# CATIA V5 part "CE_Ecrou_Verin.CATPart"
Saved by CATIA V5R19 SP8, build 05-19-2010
Part number: CE6_Ecrou_Verin
Nomenclature: 70_m
Bounding box of the stored display mesh (mm): x -18 to 18, y -17.75 to 17.75, z 15 to 135
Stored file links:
  C:\Users\rphgr\Desktop\0_Tapis_TC520B_vitesse\CE_Ecrou_Verin.CATPart
  D:\Documents\1_Travail\1 - ac-limoges.fr\ac-limoges.fr\Emmanuel Maynard - STI2D_Turgot\3 - Supports\Tapis de course TC520B\Tapis de course TC520B_Ca\Vis.CATPart
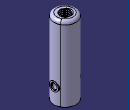
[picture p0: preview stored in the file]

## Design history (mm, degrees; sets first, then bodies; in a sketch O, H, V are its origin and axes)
AxisSystem1: origin (0, 0, 0), X (1, 0, 0), Y (0, 1, 0), Z (0, 0, 1)
AxisSystem2: origin (0, 0, 0), X (1, 0, 0), Y (0, 1, 0), Z (0, 0, 1)
Sketch1 on ZX plane of AxisSystem2, origin (0, 0, 135), H (0, 0, 1), V (1, 0, 0)
  line L1 (0, 0) -> (0, 12.75)
  arc A1 centre (-5, 12.75) radius 5 from (0, 12.75) to (-5, 17.75) ccw
  line L2 (-5, 17.75) -> (-120, 17.75)
  line L3 (-120, 17.75) -> (-120, 16.25)
  line L4 (-120, 16.25) -> (-42, 16.25)
  line L5 (-42, 16.25) -> (-42, 0)
  line L6 (-42, 0) -> (0, 0)
  distance L1 L3 = 120
  distance L5 L3 = 78
  distance L2 L6 = 17.75
  distance L2 L4 = 1.5
  radius A1 = 5
  tangency: A1 L1, L2 A1
  vertical: L3 V, L5 V
  coincidence: L6 H
Shaft1: profile Sketch1, axis Sketch1.L6, angle 360
Sketch2 on ZX plane of AxisSystem1, origin (0, 0, 0), H (0, 0, 1), V (1, 0, 0)
  axis line L1 (-8.4468, 0) -> (91.9456, 0)
  point P1 (-8.4468, 0)
  line L2 (0, 0) -> (0, 6)
  line L3 (0, 6) -> (22.1235, 6)
  line L4 (22.1235, 6) -> (51.5, 6)
  line L5 (51.5, 6) -> (51.5, 6.65)
  line L6 (51.5, 6.65) -> (53.5, 6.65)
  line L7 (53.5, 6.65) -> (53.5, 9.5)
  line L8 (53.5, 9.5) -> (145, 9.5)
  line L9 (145, 9.5) -> (145, 0)
  point P10 (145, 0)
  distance L3 L1 = 6
  distance L6 L1 = 6.65
  distance L8 L1 = 9.5
  distance L2 L5 = 51.5
  distance L5 L7 = 2
  distance L2 L9 = 145
  coincidence: P1 H, P10 L1
  horizontal: L1 H, L3 H, L4 H, L6 H, L8 H
  vertical: L2 V, L5 V, L7 V, L9 V
Shaft2: profile Sketch2, axis Sketch2.L1, angle 360
Body1 (main body)
  Body2
    Chamfer1: length 1, angle 45, on face of Shaft2 from Sketch2.L2
    Fillet1: radius 2, on edge [face of Shaft2 from Sketch2.L6 | face of Shaft2 from Sketch2.L7]
    Chamfer2: length 5, angle 30, on face of Shaft2 from Sketch2.L9
    Sketch3 on ZX plane of AxisSystem1, origin (0, 0, 0), H (0, 0, 1), V (1, 0, 0)
      line L1 (49.5, 0) -> (49.5, 9.5)
      point P1 (49.5, 0)
      point P2 (49.5, 9.5)
      reference intersected line E1 through (53.5, 0) direction (0, 1) from face of Shaft2 from Sketch2.L7
      length L1 = 9.5
      distance L1 E1 = 4
      coincidence: P1 H
      vertical: L1 V
    Helix1: Direction Z axis, RefPoint Sketch3.P2, Pitch 3, Height 100, TaperAngle 0
    Sketch4 on ZX plane of AxisSystem1, origin (0, 0, 0), H (0, 0, 1), V (1, 0, 0)
      point P1 (53.5, 9.5)
      line L1 (53.5, 9.5) -> (55.4019, 9.5)
      line L2 (55.4019, 9.5) -> (55, 8)
      line L3 (55, 8) -> (53.9019, 8)
      line L4 (53.9019, 8) -> (53.5, 9.5)
      axis line L5 (53.701, 8.75) -> (55.201, 8.75)
      point P5 (53.701, 8.75)
      point P6 (55.201, 8.75)
      reference projected line E1 through (0, 0) direction (1, 0) from axis of face of Shaft2 from Sketch2.L8
      reference intersected line E2 through (53.5, 0) direction (0, 1) from face of Shaft2 from Sketch2.L7
      reference projected line E3 through (0, 0) direction (1, 0) from axis of face of Shaft2 from Sketch2.L8
      angle L4 L2 = 30
      angle L1 L2 = 75
      distance L5 L1 = 0.75
      distance L1 E1 = 9.5
      distance L3 E3 = 8
      length L5 = 1.5
      horizontal: L1 H, L3 H, L5 H
      coincidence: P5 L4, P6 L2, P1 E2
    Slot1: profile Sketch4, centre curve Helix1
    Sketch5 on ZX plane of AxisSystem1, origin (0, 0, 0), H (0, 0, 1), V (1, 0, 0)
      circle A1 centre (19, 0) radius 2.5
      point P1 (19, 0)
      reference intersected line E1 (0, -6) -> (0, 6) from face of Shaft2 from Sketch2.L2
      radius A1 = 2.5
      distance E1 P1 = 19
      coincidence: P1 H
    Pocket1: profile Sketch5, direction (0, -1, 0), length 20, mirrored extent
    Chamfer3: length 1, angle 30, on face of Pocket1 from Sketch5.A1
  Remove1: tool Body2
  Sketch6 on YZ plane of AxisSystem2, origin (0, 0, 0), H (0, 1, 0), V (0, 0, 1)
    circle A1 centre (0, 40.6753) radius 5.1
    point P1 (0, 40.6753)
    radius A1 = 5.1
    coincidence: P1 V
  Pad1: profile Sketch6, direction (1, 0, 0), length 18, mirrored extent, thin wall 0, second thickness 2.3
  Sketch7 on start face of Pad1, origin (-18, 0, 0), H (0, -1, 0), V (0, 0, 1)
    projected circle E1 centre (0, 40.6753) radius 5.1 from edge [face of Pad1 | start face of Pad1]
  Pocket2: profile Sketch7, direction (1, 0, 0), through (limit type 3)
